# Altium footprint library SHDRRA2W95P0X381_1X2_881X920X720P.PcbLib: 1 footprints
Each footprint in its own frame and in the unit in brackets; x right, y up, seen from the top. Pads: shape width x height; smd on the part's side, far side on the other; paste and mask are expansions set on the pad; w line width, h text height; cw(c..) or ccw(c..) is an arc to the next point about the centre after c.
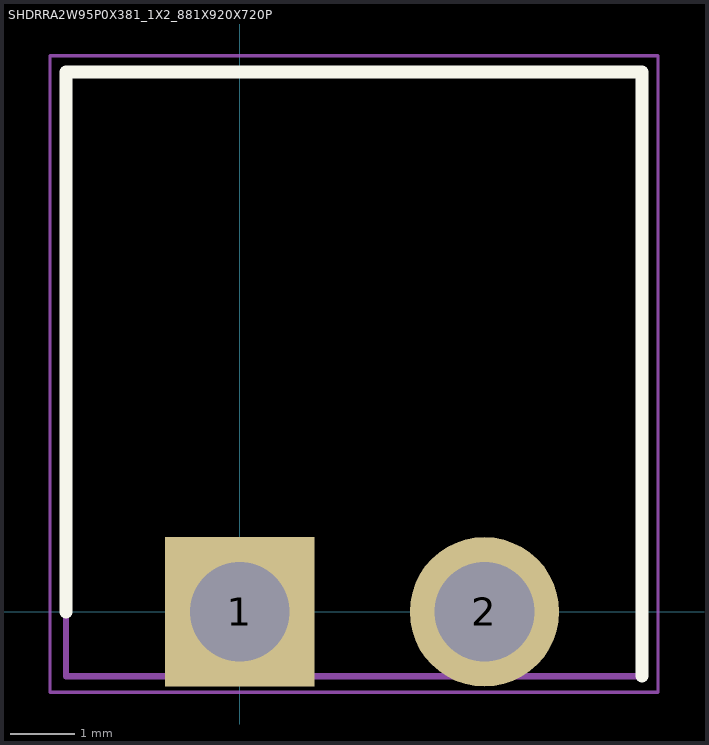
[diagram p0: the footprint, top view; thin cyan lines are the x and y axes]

## SHDRRA2W95P0X381_1X2_881X920X720P [mm]
pads (2):
  rect 2.325x2.325 / inner round 2.325 / far side rect 2.325x2.325 hole 1.55: 1(0,0)
  round 2.325 hole 1.55: 2(3.81,0)
Top Overlay:
  lines w0.2: -2.7,0 -2.7,8.4 6.26,8.4 6.26,-1
Mechanical 15:
  lines w0.1: -2.7,-1 -2.7,8.4 6.26,8.4 6.26,-1 -2.7,-1
Mechanical 20:
  lines w0.05: -2.95,-1.25 6.51,-1.25 6.51,8.65 -2.95,8.65 -2.95,-1.25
